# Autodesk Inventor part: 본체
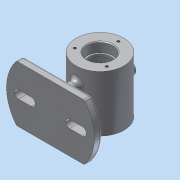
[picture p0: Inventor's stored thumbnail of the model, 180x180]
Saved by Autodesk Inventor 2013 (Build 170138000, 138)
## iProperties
Created: 2017-12
Part Number: 본체
Material: 알루미늄 6061
Document SubType Name: Modeling
Designer: dgall
Density: 2.71 g/cm^3
Mass: 467.692 g
Surface Area: 486.483 cm^2
Volume: 172.58 cm^3
Author: dgall
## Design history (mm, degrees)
sketch "스케치1"
  geometry: C1 r 30 at (0, 0); 1 further point
  constraints: 1 centre point, 1 coincident
  dimensions: "d0" = 60 diameter of C1
extrude "돌출1" new body sketch "스케치1" stored distance "d2" = 70; taper "d3" = 0 deg
node "작업 평면1"
sketch "스케치2"
  geometry: L1 (42.426, 35)-(-42.426, 35); L2 (42.426, -35)-(-42.426, -35); A1 r 55 centre (0, 0) between (42.426, -35) and (42.426, 35); A2 r 55 centre (0, 0) between (-42.426, 35) and (-42.426, -35); 2 further points
  constraints: 4 end point, 4 point on circle, 2 centre point, 2 parallel, 1 coincident, 1 horizontal, 1 midpoint, 1 vertical alignment
  dimensions: "d7" = 70 distance between parallel lines of L2 L1; "d9" = 55 radius of A2
extrude "돌출2" join sketch "스케치2" distance "d10" = 10; taper "d11" = 0 deg
fillet "모깎기1" dims "d12" = 3
fillet "모깎기2" dims "d13" = 3
sketch "스케치3"
  geometry: L1 (-40, -5)-(-24, -5); L2 (-40, 5)-(-24, 5); L3 (40, -5)-(24, -5); L4 (24, 5)-(40, 5); A1 r 52 centre (0, 0) between (40.988, -32) and (40.988, 32) reference; A2 r 5 centre (-40, 0) between (-40, 5) and (-40, -5); A3 r 5 centre (-24, 0) between (-24, -5) and (-24, 5); A4 r 5 centre (24, 0) between (24, 5) and (24, -5); A5 r 5 centre (40, 0) between (40, -5) and (40, 5)
  constraints: 8 end point, 8 point on circle, 6 tangent, 4 centre point, 4 horizontal alignment, 2 parallel, 1 equal radius, 1 horizontal
  dimensions: "d14" = 16 distance of A2.centre A3.centre; "d16" = 24 distance of A3.centre A1.centre; "d17" = 16 distance of A5.centre A4.centre; "d18" = 24 distance of A1.centre A4.centre; "d19" = 5 radius of A2; "d20" = 5 radius of A4
extrude "돌출3" cut sketch "스케치3" distance "d21" = 10; taper "d22" = 0 deg
sketch "스케치4"
  geometry: L1 (-40.988, 32)-(40.988, 32) reference; L2 (5, 15)-(5, -15); L3 (-5, 15)-(-5, -15); A1 r 52 centre (0, 0) between (40.988, -32) and (40.988, 32) reference; A2 r 5 centre (0, 15) between (5, 15) and (-5, 15); A3 r 5 centre (0, -15) between (-5, -15) and (5, -15); 1 further point
  constraints: 4 end point, 4 point on circle, 2 centre point, 2 tangent, 2 vertical alignment, 1 equal radius, 1 horizontal alignment, 1 midpoint, 1 perpendicular
  dimensions: "d23" = 5 radius of A2; "d25" = 30 distance of A3.centre A2.centre; "d26" = 15 distance of A2.centre A1.centre
extrude "돌출4" join sketch "스케치4" stored distance "d27" = 10; taper "d28" = 0 deg
fillet "모깎기3" dims "d29" = 5
node "작업 평면2"
sketch "스케치5"
  geometry: C1 r 8 at (0, 0); 1 further point
  constraints: 1 centre point, 1 coincident
  dimensions: "d31" = 16 diameter of C1
extrude "돌출5" join sketch "스케치5" stored distance "d33" = 10; taper "d34" = 0 deg
sketch "스케치6"
  geometry: L1 (-30, -35)-(30, -35) reference; L2 (30, 35)-(-30, 35) reference; L3 (0, -35)-(0, 35); L4 (0, -35)-(16, -35); L5 (16, -35)-(16, -23); L6 (16, -23)-(14, -23); L7 (14, -23)-(14, -20); L8 (14, -20)-(22, -20); L9 (25, -17)-(25, 17); L10 (22, 20)-(14, 20); L11 (14, 20)-(14, 23); L12 (14, 23)-(16, 23); L13 (16, 23)-(16, 35); L14 (16, 35)-(0, 35); A1 r 3 centre (22, 17) between (25, 17) and (22, 20); A2 r 3 centre (22, -17) between (22, -20) and (25, -17); 1 further point
  constraints: 24 end point, 5 parallel, 4 point on circle, 4 tangent, 3 collinear, 3 perpendicular, 2 centre point, 2 midpoint, 2 point on line, 1 equal radius, 1 horizontal
  dimensions: "d35" = 28 diameter of L7 L3; "d37" = 32 diameter of L5 L3; "d38" = 32 diameter of L13 L3; "d39" = 28 diameter of L11 L3; "d40" = 50 diameter of L9 L3; "d41" = 40 distance between parallel lines of L10 L8; "d42" = 12 distance of L4.end L5.end; "d43" = 3 radius of A1
revolve "회전1" sketch "스케치6" stored, may be unused: angle "d44" = 90 deg
fillet "모깎기4" dims "d45" = 0.3
chamfer "모따기1" distance "d46" = 1; stored, may be unused: second distance "d47" = 2, angle "d48" = 45 deg
chamfer "모따기2" distance "d49" = 1; stored, may be unused: second distance "d50" = 2, angle "d51" = 45 deg
hole "구멍1" diameter "d54" = 8; stored, may be unused: countersink angle "d58" = 90 deg, drill point angle "d60" = 0 deg; dims "d52" = 10, "d53" = 10, "d55" = 6, "d56" = 4, "d57" = 2, "d59" = 8
chamfer "모따기3" distance "d61" = 1; stored, may be unused: second distance "d62" = 2, angle "d63" = 45 deg
sketch "스케치7" dims "d64" = 46
  geometry: C1 r 30 at (0, 0) reference; C2 r 17 at (0, 0) reference; 2 further points
  constraints: 2 vertical alignment, 1 coincident, 2 other
hole "구멍2" sketch "스케치7" at (0, 23) diameter "d66" = 3.242; stored, may be unused: countersink angle "d70" = 90 deg, drill point angle "d72" = 118 deg; dims "d67" = 8, "d68" = 4, "d69" = 2, "d71" = 10
fillet "모깎기5" dims "d76" = 3
node "작업 평면3"
sketch "스케치8"
  geometry: L1 (-30, -35)-(-30, 35) reference; L2 (-30, -35)-(30, -35) reference; 2 further points
  constraints: 1 other
  dimensions: "d78" = 30 distance from line of L1 point (0, 0); "d79" = 35 distance from line of point (0, 0) L2
feature "엠보싱1" sketch "스케치8" dims "d80" = 0.5, "d81" = 0
node "솔리드1"
pattern_circular "원형 패턴1" dims angle "d74" = 360 deg
mirror "대칭1"
other parameters: "d4" = -62, "d30" = 37
